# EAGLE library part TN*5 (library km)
8-bit-Mikrocontroller 2/4/8 KByte Flash (selbstprogrammierbar) 128/256/512 Byte RAM 128/256/512 Byte EEPROM 4x ADC, 4x PWM (8 Bit), Totzeitgenerator, 1x USI (SPI oder I²C)
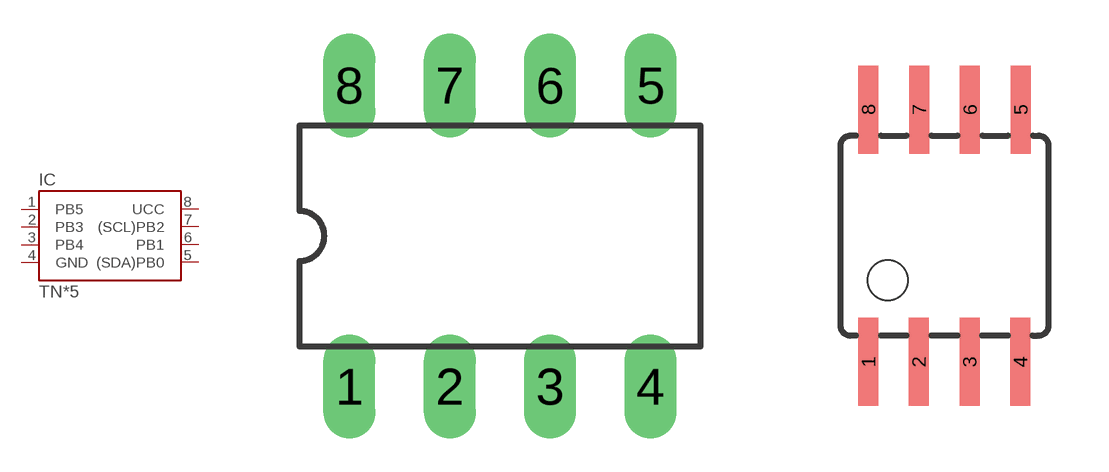
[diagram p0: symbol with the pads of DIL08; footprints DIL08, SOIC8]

Designator prefix IC

## TN25P, TN45P, TN85P  [DIL08]
1  PB5
2  PB3
3  PB4
4  GND  pwr
5  (SDA)PB0
6  PB1
7  (SCL)PB2
8  UCC  pwr

## TN5S  [SOIC8]
Pads as for DIL08

## Footprint DIL08 (pad centres in mm)
Dual In Line
drill 0.813 long: 1 -3.81,-3.81; 2 -1.27,-3.81; 3 1.27,-3.81; 4 3.81,-3.81; 5 3.81,3.81; 6 1.27,3.81; 7 -1.27,3.81; 8 -3.81,3.81

## Footprint SOIC8 (pad centres in mm)
Wide Plastic Gull Wing Small Outline Package
smd 0.5 x 2.2: 1 -1.905,-3.154; 2 -0.645,-3.154; 3 0.625,-3.154; 4 1.895,-3.154; 5 1.905,3.154; 6 0.635,3.154; 7 -0.635,3.154; 8 -1.905,3.154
